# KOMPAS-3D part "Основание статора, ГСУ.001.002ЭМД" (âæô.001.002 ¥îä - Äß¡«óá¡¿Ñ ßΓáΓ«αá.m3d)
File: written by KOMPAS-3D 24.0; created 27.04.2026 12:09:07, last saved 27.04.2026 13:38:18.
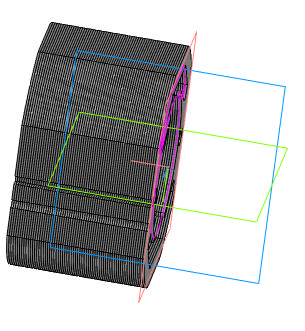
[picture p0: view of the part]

Document properties: Автор: USG_411; Полное имя файла: C:\Users\USG_411.STUD\Desktop\ГМ2704_411-23\Двигатель мясорубки\ГСУ.001.002 ЭМД - Пластина.m3d

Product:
- Body: Тело 1  | qty 1  | 64 such rows
    Масса: 0.003893
- Part/product: Основание статора  | designation ГСУ.001.002ЭМД
    Масса: 0.249145

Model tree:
1. Эскиз:1
2. Элемент выдавливания:1
3. Эскиз:2  (with: Грань.Элемент выдавливания:1, Ребро.Элемент выдавливания:1)
4. Элемент выдавливания:2
     Расстояние 2 = 10
5. Зеркальный массив:1
6. Экземпляр ( 1 )
7. Экземпляр ( 2 )  (with: Элемент выдавливания:2)
8. Зеркальный массив:2  (with: Экземпляр ( 1 ), Экземпляр ( 2 ), Зеркальный массив:1, Элемент выдавливания:2)
9. Эскиз:3  (with: Грань.Элемент выдавливания:1, Ребро.Элемент выдавливания:1)
10. Элемент выдавливания:4
     Расстояние 2 = 10
11. Элемент выдавливания:6
     Расстояние 2 = 10
12. Зеркальный массив:3  (with: Экземпляр ( 1 ), Экземпляр ( 2 ), Элемент выдавливания:6)
13. Эскиз:4  (with: Грань.Элемент выдавливания:1, Ребро.Элемент выдавливания:1)
14. Элемент выдавливания:7
     Расстояние 2 = 10
15. Зеркальный массив:4  (with: Экземпляр ( 1 ), Экземпляр ( 2 ), Элемент выдавливания:7)
16. Эскиз:5  (with: Ребро.Элемент выдавливания:1)
17. Элемент выдавливания:8
     Расстояние 2 = 10
18. Массив по сетке:1  (2 pattern instances)
19. Тело 1  (62 pattern instances)
     Угол раствора = 90; Шаг 2 = 10

Expressions: 36.3/2; 17.2/2; v14+0.02
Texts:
  ГСУ.001.002
  ГСУ.001.002 ЭМД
